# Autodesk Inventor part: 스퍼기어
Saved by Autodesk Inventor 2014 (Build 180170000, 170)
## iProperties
Created: 2026-03
Part Number: 스퍼기어
Material: 일반
Document SubType Name: Modeling
Designer: dg
Density: 1 g/cm^3
Appearance: 기본값
Author: dg
Author: jhkim
Creation Date: 2025-06-27
Sending System: Autodesk Inventor 2026
Preprocessor: ST-DEVELOPER v20.1
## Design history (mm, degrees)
node "스퍼기어1"
node "솔리드1"
node "기준1"
